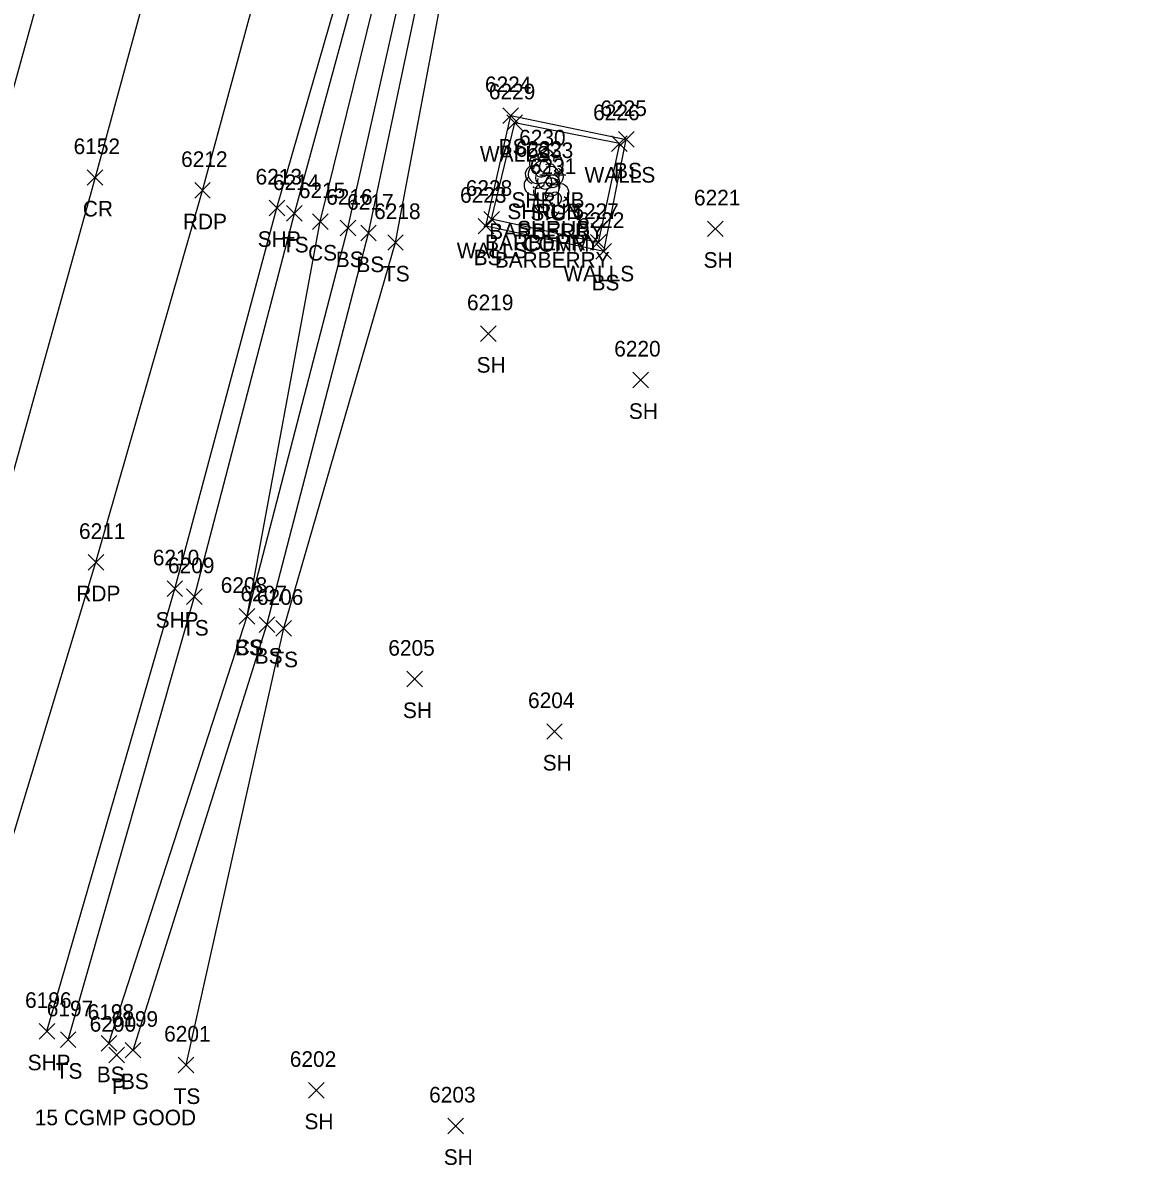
# Model space of a CAD drawing. Extents: x 1443912 to 1445411, y 621446 to 623693.
# Drawn here: x 1444452.6 to 1444596.2, y 621445.6 to 621592 of the extents above; entities that cross this region are included whole.
import ezdxf

# ---------------------------------------------------------------- set-up
doc = ezdxf.new("R2010")
doc.units = 0
for name, color, linetype in [('D_A', 7, 'Continuous'), ('D_C', 7, 'Continuous'), ('D_I', 7, 'Continuous'), ('D_TIC', 7, 'Continuous'), ('L_A', 7, 'Continuous'), ('L_C', 7, 'Continuous'), ('L_I', 7, 'Continuous'), ('L_TIC', 7, 'Continuous'), ('LELB', 7, 'Continuous'), ('LSH', 7, 'Continuous'), ('LWS', 7, 'Continuous'), ('P_A', 7, 'Continuous'), ('P_I', 7, 'Continuous'), ('P_TIC', 7, 'Continuous'), ('PET', 7, 'Continuous'), ('PRC', 7, 'Continuous'), ('PSP', 7, 'Continuous'), ('S_A', 7, 'Continuous'), ('S_C', 7, 'Continuous'), ('S_I', 7, 'Continuous'), ('SSGN', 7, 'Continuous')]:
    doc.layers.add(name, color=color, linetype=linetype)

msp = doc.modelspace()

# ---------------------------------------------------------------- linework, layer by layer
at = {"layer": 'D_TIC'}
for points in [[(1444463.61, 621458.7), (1444465.61, 621460.7)], [(1444465.61, 621458.7), (1444463.61, 621460.7)]]:
    msp.add_lwpolyline(points, dxfattribs=at)
at = {"layer": 'L_TIC'}
for points in [[(1444514.09, 621579.14), (1444516.09, 621581.14)], [(1444516.09, 621579.14), (1444514.09, 621581.14)], [(1444514.59, 621578.22), (1444516.59, 621580.22)], [(1444516.59, 621578.22), (1444514.59, 621580.22)], [(1444514.59, 621578.22), (1444516.59, 621580.22)], [(1444516.59, 621578.22), (1444514.59, 621580.22)], [(1444528, 621575.54), (1444530, 621577.54)], [(1444530, 621575.54), (1444528, 621577.54)], [(1444528, 621575.54), (1444530, 621577.54)], [(1444530, 621575.54), (1444528, 621577.54)], [(1444528.88, 621576.08), (1444530.88, 621578.08)], [(1444530.88, 621576.08), (1444528.88, 621578.08)], [(1444528.88, 621576.08), (1444530.88, 621578.08)], [(1444530.88, 621576.08), (1444528.88, 621578.08)], [(1444486.36, 621566.59), (1444488.36, 621568.59)], [(1444488.36, 621566.59), (1444486.36, 621568.59)], [(1444489.68, 621565.55), (1444491.68, 621567.55)], [(1444491.68, 621565.55), (1444489.68, 621567.55)], [(1444493.23, 621564.71), (1444495.23, 621566.71)], [(1444495.23, 621564.71), (1444493.23, 621566.71)], [(1444510.9, 621564.96), (1444512.9, 621566.96)], [(1444512.9, 621564.96), (1444510.9, 621566.96)], [(1444511.63, 621565.85), (1444513.63, 621567.85)], [(1444513.63, 621565.85), (1444511.63, 621567.85)], [(1444540.3, 621564.62), (1444542.3, 621566.62)], [(1444542.3, 621564.62), (1444540.3, 621566.62)], [(1444495.86, 621564.07), (1444497.86, 621566.07)], [(1444497.86, 621564.07), (1444495.86, 621566.07)], [(1444499.32, 621562.87), (1444501.32, 621564.87)], [(1444501.32, 621562.87), (1444499.32, 621564.87)], [(1444525.29, 621562.88), (1444527.29, 621564.88)], [(1444527.29, 621562.88), (1444525.29, 621564.88)], [(1444526, 621561.73), (1444528, 621563.73)], [(1444528, 621561.73), (1444526, 621563.73)], [(1444526, 621561.73), (1444528, 621563.73)], [(1444528, 621561.73), (1444526, 621563.73)], [(1444511.23, 621551.18), (1444513.23, 621553.18)], [(1444513.23, 621551.18), (1444511.23, 621553.18)], [(1444530.73, 621545.25), (1444532.73, 621547.25)], [(1444532.73, 621545.25), (1444530.73, 621547.25)], [(1444473.56, 621517.47), (1444475.56, 621519.47)], [(1444475.56, 621517.47), (1444473.56, 621519.47)], [(1444480.31, 621514.95), (1444482.31, 621516.95)], [(1444482.31, 621514.95), (1444480.31, 621516.95)], [(1444480.31, 621514.95), (1444482.31, 621516.95)], [(1444482.31, 621514.95), (1444480.31, 621516.95)], [(1444482.84, 621513.87), (1444484.84, 621515.87)], [(1444484.84, 621513.87), (1444482.84, 621515.87)], [(1444485, 621513.41), (1444487, 621515.41)], [(1444487, 621513.41), (1444485, 621515.41)], [(1444501.79, 621506.9), (1444503.79, 621508.9)], [(1444503.79, 621506.9), (1444501.79, 621508.9)], [(1444519.69, 621500.18), (1444521.69, 621502.18)], [(1444521.69, 621500.18), (1444519.69, 621502.18)], [(1444457.38, 621460.67), (1444459.38, 621462.67)], [(1444459.38, 621460.67), (1444457.38, 621462.67)], [(1444462.61, 621460.22), (1444464.61, 621462.22)], [(1444464.61, 621460.22), (1444462.61, 621462.22)], [(1444465.7, 621459.33), (1444467.7, 621461.33)], [(1444467.7, 621459.33), (1444465.7, 621461.33)], [(1444472.49, 621457.43), (1444474.49, 621459.43)], [(1444474.49, 621457.43), (1444472.49, 621459.43)], [(1444489.17, 621454.19), (1444491.17, 621456.19)], [(1444491.17, 621454.19), (1444489.17, 621456.19)], [(1444507.02, 621449.62), (1444509.02, 621451.62)], [(1444509.02, 621449.62), (1444507.02, 621451.62)]]:
    msp.add_lwpolyline(points, dxfattribs=at)
at = {"layer": 'LELB'}
for points in [[(1444458.38, 621461.67), (1444474.56, 621518.47), (1444487.36, 621567.59), (1444499.52, 621612.21), (1444507.75, 621640.81), (1444515.8, 621646.74), (1444520.62, 621648.14), (1444537.21, 621650.23), (1444558.7, 621643.2)], [(1444463.61, 621461.22), (1444481.31, 621515.95), (1444494.23, 621565.71), (1444504.32, 621610.71), (1444510.98, 621634.9), (1444513.69, 621641.62), (1444516.52, 621644.2), (1444521.5, 621646.32), (1444536.4, 621646.84), (1444558.18, 621640.41)], [(1444473.49, 621458.43), (1444486, 621514.41), (1444500.32, 621563.87), (1444508.93, 621609.66), (1444521.5, 621646.32)], [(1444481.31, 621515.95), (1444490.68, 621566.55), (1444501.75, 621611.58), (1444509.02, 621640.43), (1444515.8, 621646.74)], [(1444466.7, 621460.33), (1444483.84, 621514.87), (1444496.86, 621565.07), (1444506.39, 621610.17), (1444516.52, 621644.2)], [(1444527, 621562.73), (1444511.9, 621565.96), (1444515.09, 621580.14), (1444529.88, 621577.08)], [(1444527, 621562.73), (1444529.88, 621577.08)]]:
    msp.add_lwpolyline(points, dxfattribs=at)
at = {"layer": 'LSH'}
for p, q in [((1444519.55, 621573.31), (1444519.55, 621573.31)), ((1444519.55, 621573.31), (1444519.55, 621573.31)), ((1444519.02, 621571.86), (1444519.02, 621571.86)), ((1444519.02, 621571.86), (1444519.02, 621571.86)), ((1444520.27, 621569.64), (1444520.27, 621569.64)), ((1444520.27, 621569.64), (1444520.27, 621569.64))]:
    msp.add_line(p, q, dxfattribs=at)
for centre in [(1444519.6, 621574.74), (1444519.07, 621573.29), (1444520.32, 621571.08)]:
    msp.add_arc(centre, 1.05, 335.5272, 180.9563, dxfattribs=at)
for centre, major_axis, ratio, start_param, end_param in [((1444518.76, 621573.98), (1.21, -0.51), 0.895232, 1.570796, 4.712389), ((1444518.23, 621572.52), (1.21, -0.51), 0.895232, 1.570796, 4.712389), ((1444519.34, 621573.77), (-0.208, -0.792), 0.645439, 3.141593, 6.283185), ((1444520.05, 621573.14), (-0.5, 0.667), 0.989748, 3.141593, 6.283185), ((1444520.07, 621572.44), (-1.14, -0.48), 0.949671, 1.570796, 4.712389), ((1444520.59, 621573.89), (-1.14, -0.48), 0.949671, 1.570796, 4.712389), ((1444518.47, 621572.6), (0.58, -1.04), 0.959034, 3.141593, 6.283185), ((1444518.82, 621572.31), (-0.208, -0.792), 0.645439, 3.141593, 6.283185), ((1444519.09, 621572.56), (-0.625, -0.083), 0.423636, 0, 3.141593), ((1444519.52, 621571.69), (-0.5, 0.667), 0.989748, 3.141593, 6.283185), ((1444520.55, 621572.48), (-1.09, 0.79), 0.841452, 1.570796, 4.712389), ((1444517.94, 621571.15), (0.58, -1.04), 0.959034, 3.141593, 6.283185), ((1444518.57, 621571.11), (-0.625, -0.083), 0.423636, 0, 3.141593), ((1444519.48, 621570.31), (1.21, -0.51), 0.895232, 1.570796, 4.712389), ((1444519.55, 621571.81), (0.26, 1.06), 0.942809, 1.570796, 4.712389), ((1444520.02, 621571.02), (-1.09, 0.79), 0.841452, 1.570796, 4.712389), ((1444520.06, 621570.1), (-0.208, -0.792), 0.645439, 3.141593, 6.283185), ((1444521.31, 621570.23), (-1.14, -0.48), 0.949671, 1.570796, 4.712389), ((1444519.19, 621568.94), (0.58, -1.04), 0.959034, 3.141593, 6.283185), ((1444519.02, 621570.36), (0.26, 1.06), 0.942809, 1.570796, 4.712389), ((1444520.77, 621569.48), (-0.5, 0.667), 0.989748, 3.141593, 6.283185), ((1444521.27, 621568.81), (-1.09, 0.79), 0.841452, 1.570796, 4.712389), ((1444520.27, 621568.14), (0.26, 1.06), 0.942809, 1.570796, 4.712389), ((1444519.81, 621568.89), (-0.625, -0.083), 0.423636, 0, 3.141593)]:
    msp.add_ellipse(centre, major_axis=major_axis, ratio=ratio, start_param=start_param, end_param=end_param, dxfattribs=at)
at = {"layer": 'LWS'}
for points in [[(1444529, 621576.54), (1444526.29, 621563.88), (1444512.63, 621566.85), (1444515.59, 621579.22)], [(1444529, 621576.54), (1444515.59, 621579.22)]]:
    msp.add_lwpolyline(points, dxfattribs=at)
at = {"layer": 'P_TIC'}
for points in [[(1444460.82, 621571.2), (1444462.82, 621573.2)], [(1444462.82, 621571.2), (1444460.82, 621573.2)], [(1444474.59, 621569.55), (1444476.59, 621571.55)], [(1444476.59, 621569.55), (1444474.59, 621571.55)], [(1444484.13, 621567.3), (1444486.13, 621569.3)], [(1444486.13, 621567.3), (1444484.13, 621569.3)], [(1444460.94, 621521.87), (1444462.94, 621523.87)], [(1444462.94, 621521.87), (1444460.94, 621523.87)], [(1444471.05, 621518.48), (1444473.05, 621520.48)], [(1444473.05, 621518.48), (1444471.05, 621520.48)], [(1444454.66, 621461.75), (1444456.66, 621463.75)], [(1444456.66, 621461.75), (1444454.66, 621463.75)]]:
    msp.add_lwpolyline(points, dxfattribs=at)
at = {"layer": 'PET'}
for points in [[(1444707.78, 622511.05), (1444700.03, 622482.58), (1444691.73, 622453.67), (1444679.73, 622411.23), (1444667.69, 622368.84), (1444653.08, 622317.67), (1444637.74, 622256.92), (1444626.42, 622209.58), (1444619.02, 622182.67), (1444605.37, 622130.08), (1444589.4, 622078.61), (1444578.44, 622026.86), (1444565.52, 621990.05), (1444556.87, 621958.17), (1444542.16, 621907.74), (1444529.8, 621863.07), (1444511.99, 621799.88), (1444498.16, 621751.76), (1444483.13, 621697.3), (1444470.84, 621653.16), (1444463.41, 621627.34), (1444449.07, 621575.52), (1444430.26, 621508.83), (1444421.17, 621471.46)], [(1444444.37, 621464.94), (1444461.94, 621522.87), (1444475.59, 621570.55), (1444487.99, 621616.26), (1444502.92, 621667.73), (1444516.83, 621718.16), (1444526.41, 621751.49), (1444537.28, 621789.32), (1444558.59, 621865), (1444573.59, 621917.93), (1444597.58, 621998.81), (1444610.14, 622044.19), (1444623.48, 622089.5), (1444632.2, 622118.09)]]:
    msp.add_lwpolyline(points, dxfattribs=at)
at = {"layer": 'PRC'}
msp.add_lwpolyline([(1444618.32, 622127.38), (1444604.97, 622075.74), (1444590.11, 622023.77), (1444578.57, 621985.29), (1444569.73, 621954.72), (1444555.25, 621903.96), (1444542.35, 621859.58), (1444524.46, 621796.02), (1444511.19, 621747.94), (1444495.68, 621693.61), (1444483.2, 621649.28), (1444475.93, 621623.97), (1444461.82, 621572.2), (1444443.22, 621505.41), (1444432.75, 621467.94)], dxfattribs=at)
at = {"layer": 'PSP'}
msp.add_lwpolyline([(1444455.66, 621462.75), (1444472.05, 621519.48), (1444485.13, 621568.3), (1444497.88, 621612.67), (1444505.4, 621638.58), (1444519.01, 621689.59), (1444525.59, 621713.97), (1444535.94, 621748.74), (1444541.51, 621770.15), (1444550.94, 621803.78), (1444567.68, 621862.81), (1444582.56, 621915.85), (1444597.67, 621969.6), (1444608.45, 622008), (1444628.13, 622076.36), (1444639.3, 622115.36)], dxfattribs=at)
at = {"layer": 'SSGN'}
for p, q in [((1444518.82, 621572.54), (1444522.15, 621572.54)), ((1444520.47, 621571.71), (1444520.47, 621571.71))]:
    msp.add_line(p, q, dxfattribs=at)
msp.add_circle((1444520.47, 621571.71), 0.833, dxfattribs=at)

# ---------------------------------------------------------------- texts
at = {"layer": 'D_A'}
msp.add_text('P', height=2, dxfattribs=at).set_placement((1444463.99, 621454.7))
at = {"layer": 'D_C'}
msp.add_text('15 CGMP GOOD', height=2, dxfattribs=at).set_placement((1444454.11, 621450.7))
at = {"layer": 'D_I'}
msp.add_text('6200', height=2, dxfattribs=at).set_placement((1444461.14, 621462.7))
at = {"layer": 'L_A'}
for s, p in [('BS', (1444513.53, 621575.14)), ('WALLS', (1444511.14, 621574.22)), ('WALLS', (1444511.14, 621574.22)), ('BS', (1444528.32, 621572.08)), ('BS', (1444528.32, 621572.08)), ('WALLS', (1444524.54, 621571.54)), ('WALLS', (1444524.54, 621571.54)), ('SHRUB', (1444515.18, 621568.31)), ('SHRUB', (1444514.65, 621566.86)), ('SHRUB', (1444515.9, 621564.64)), ('TS', (1444485.77, 621562.59)), ('CS', (1444489.12, 621561.55)), ('WALLS', (1444508.17, 621561.85)), ('BS', (1444492.67, 621560.71)), ('BS', (1444495.31, 621560.07)), ('BS', (1444510.34, 621560.96)), ('SH', (1444539.79, 621560.62)), ('TS', (1444498.72, 621558.87)), ('WALLS', (1444521.83, 621558.88)), ('BS', (1444525.44, 621557.73)), ('BS', (1444525.44, 621557.73)), ('SH', (1444510.71, 621547.18)), ('SH', (1444530.22, 621541.25)), ('TS', (1444472.97, 621513.47)), ('CS', (1444479.75, 621510.95)), ('BS', (1444479.75, 621510.95)), ('BS', (1444482.28, 621509.87)), ('TS', (1444484.41, 621509.41)), ('SH', (1444501.27, 621502.9)), ('SH', (1444519.18, 621496.18)), ('TS', (1444456.79, 621456.67)), ('BS', (1444462.05, 621456.22)), ('BS', (1444465.14, 621455.33)), ('TS', (1444471.9, 621453.43)), ('SH', (1444488.66, 621450.19)), ('SH', (1444506.51, 621445.62))]:
    msp.add_text(s, height=2, dxfattribs=at).set_placement(p)
at = {"layer": 'L_C'}
for p in [(1444512.32, 621564.31), (1444511.8, 621562.86), (1444513.04, 621560.64)]:
    msp.add_text('BARBERRY', height=2, dxfattribs=at).set_placement(p)
at = {"layer": 'L_I'}
for s, p in [('6224', (1444511.78, 621583.14)), ('6229', (1444512.28, 621582.22)), ('6229', (1444512.28, 621582.22)), ('6226', (1444525.64, 621579.54)), ('6226', (1444525.64, 621579.54)), ('6225', (1444526.57, 621580.08)), ('6225', (1444526.57, 621580.08)), ('6230', (1444516.16, 621576.31)), ('6232', (1444515.72, 621574.86)), ('6231', (1444517.53, 621572.64)), ('6214', (1444484.62, 621570.59)), ('6215', (1444487.94, 621569.55)), ('6223', (1444508.59, 621568.96)), ('6228', (1444509.32, 621569.85)), ('6216', (1444491.44, 621568.71)), ('6217', (1444494.12, 621568.07)), ('6221', (1444538.56, 621568.62)), ('6218', (1444497.58, 621566.87)), ('6227', (1444522.98, 621566.88)), ('6222', (1444523.69, 621565.73)), ('6222', (1444523.69, 621565.73)), ('6219', (1444509.48, 621555.18)), ('6220', (1444528.34, 621549.25)), ('6209', (1444471.17, 621521.47)), ('6208', (1444477.93, 621518.95)), ('6208', (1444477.93, 621518.95)), ('6207', (1444480.46, 621517.87)), ('6206', (1444482.56, 621517.41)), ('6205', (1444499.4, 621510.9)), ('6204', (1444517.3, 621504.18)), ('6197', (1444455.64, 621464.67)), ('6198', (1444460.87, 621464.22)), ('6199', (1444463.95, 621463.33)), ('6201', (1444470.68, 621461.43)), ('6202', (1444486.78, 621458.19)), ('6203', (1444504.63, 621453.62))]:
    msp.add_text(s, height=2, dxfattribs=at).set_placement(p)
at = {"layer": 'P_A'}
for s, p in [('CR', (1444460.26, 621567.2)), ('RDP', (1444473.08, 621565.55)), ('SHP', (1444482.67, 621563.3)), ('RDP', (1444459.43, 621517.87)), ('SHP', (1444469.59, 621514.48)), ('SHP', (1444453.19, 621457.75))]:
    msp.add_text(s, height=2, dxfattribs=at).set_placement(p)
at = {"layer": 'P_I'}
for s, p in [('6152', (1444459.08, 621575.2)), ('6212', (1444472.85, 621573.55)), ('6213', (1444482.39, 621571.3)), ('6211', (1444459.77, 621525.87)), ('6210', (1444469.23, 621522.48)), ('6196', (1444452.86, 621465.75))]:
    msp.add_text(s, height=2, dxfattribs=at).set_placement(p)
at = {"layer": 'S_A'}
msp.add_text('SIGN', height=2, dxfattribs=at).set_placement((1444517.6, 621566.69))
at = {"layer": 'S_C'}
msp.add_text('COMM', height=2, dxfattribs=at).set_placement((1444516.71, 621562.69))
at = {"layer": 'S_I'}
msp.add_text('6233', height=2, dxfattribs=at).set_placement((1444517.14, 621574.69))

doc.saveas('drawing.dxf')
